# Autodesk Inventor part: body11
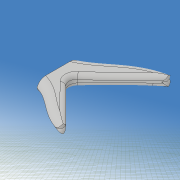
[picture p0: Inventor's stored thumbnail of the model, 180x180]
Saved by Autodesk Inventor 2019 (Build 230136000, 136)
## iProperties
Created: 2020-12
Part Number: body11
Material: 一般
Document SubType Name: Modeling
Designer: kikut
Density: 1 g/cm^3
Appearance: 既定
Mass: 87.6477 g
Surface Area: 156.124 cm^2
Volume: 87.6477 cm^3
Author: kikut
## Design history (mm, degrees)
sketch "スケッチ1"
  geometry: L1 (-100, -20)-(100, -20); L2 (100, -20)-(100, 20); L3 (100, 20)-(-100, 20); L4 (-100, 20)-(-100, -20); L5 (-100, -20)-(100, 20); L6 (100, -20)-(-100, 20); 1 further point
  constraints: 12 end point, 2 midpoint, 2 parallel, 1 horizontal, 1 perpendicular
  dimensions: "d0" = 40 distance of L3.end L1.start; "d1" = 200 distance of L2.end L3.end
extrude "押し出し1" new body sketch "スケッチ1" stored distance "d2" = 60; taper "d3" = 0 deg
sketch "スケッチ2"
  geometry: L1 (0, -60)-(0, 0) reference; L2 (200, -60)-(200, 0) reference; L3 (0, 0)-(200, 0) reference; L4 (200, -60)-(0, -60) reference; L5 (0, -26)-(0, -32); L6 (194, -10)-(194, -13); L7 (194, -13)-(174, -33); L8 (174, -33)-(200, -58); L9 (-20, 20)-(220, 20); L10 (220, 20)-(220, -100); L11 (220, -100)-(-20, -100); L12 (-20, -100)-(-20, 20); 12 further points
  constraints: 16 end point, 4 point on line, 2 parallel, 2 vertical, 1 horizontal, 1 perpendicular, 14 other
  dimensions: "d4" = 32 distance from line of point (32, -12) L1; "d5" = 50 horizontal distance of point (32, -12) point (82, -11); "d6" = 50 horizontal distance of point (132, -17) point (82, -11); "d7" = 12 distance from line of point (32, -12) L3; "d8" = 11 distance from line of point (82, -11) L3; "d10" = 17 distance from line of point (132, -17) L3; "d11" = 26 distance from line of L5.start L3; "d12" = 0 distance from line of point (200, -60) L4; "d13" = 28 distance from line of L5.end L4; "d14" = 12 distance from line of point (28, -48) L4; "d15" = 10 distance from line of point (80, -50) L4; "d16" = 16 distance from line of point (130, -44) L4; "d17" = 28 distance from line of point (28, -48) L1; "d19" = 50 horizontal distance of point (130, -44) point (80, -50); "d20" = 80 distance from line of point (80, -50) L1; "d21" = 6 distance from line of L6.start L2; "d22" = 36 distance from line of point (164, -24) L2; "d23" = 24 distance from line of point (176, -20) L2; "d24" = 10 distance from line of L6.start L3; "d25" = 20 distance from line of point (176, -20) L3; "d26" = 24 distance from line of point (164, -24) L3; "d27" = 40 distance from line of point (160, -40) L2; "d28" = 25 distance from line of point (175, -47.5) L2; "d29" = 12.5 distance from line of point (175, -47.5) L4; "d30" = 20 distance from line of L4 point (160, -40); "d31" = 3 distance of L6.start L6.end; "d32" = 33 distance from line of L7.end L3; "d33" = 26 distance from line of L7.end L2; "d34" = 2 distance of L8.end L2.start; "d35" = 120 distance of L11.end L9.start; "d36" = 240 distance of L10.end L11.end; "d37" = 20 distance between parallel lines of L1 L12; "d38" = 20 distance between parallel lines of L3 L9
extrude "押し出し2" cut sketch "スケッチ2" extent not by distance; stored distance "d39" = 0.02; taper "d40" = 0 deg
sketch "スケッチ8"
  geometry: L1 (-100, -20)-(-100, 20) reference; L2 (100, 20)-(100, -20) reference; L3 (-142.805, 0)-(142.831, 0) reference; L4 (110, 30)-(-110, 30); L5 (-110, 30)-(-110, -30); L6 (-110, -30)-(110, -30); L7 (110, -30)-(110, 30); L8 (110, 30)-(-110, -30); L9 (-110, 30)-(110, -30); L10 (-100, -2)-(-100, 2); L11 (100, -3)-(100, 3); 7 further points
  constraints: 16 end point, 4 point on line, 2 midpoint, 2 parallel, 2 perpendicular, 1 collinear, 1 horizontal, 10 other
  dimensions: "d93" = 2 vertical distance of point (0, 0) L10.end; "d94" = 2 vertical distance of L10.start point (0, 0); "d95" = 35 distance from line of point (-65, -10) L1; "d96" = 0 horizontal distance of point (-65, 10) point (-65, -10); "d97" = 10 vertical distance of point (0, 0) point (-65, -10); "d98" = 10 vertical distance of point (-65, 10) point (0, 0); "d99" = 100 distance from line of point (0, -10) L1; "d100" = 0 horizontal distance of point (0, 10) point (0, -10); "d101" = 10 distance of point (0, -10) point (0, 0); "d102" = 10 distance of point (0, 0) point (0, 10); "d103" = 160 distance from line of point (60, -4) L1; "d104" = 0 horizontal distance of point (60, 4) point (60, -4); "d105" = 4 distance from line of L3 point (60, -4); "d106" = 4 distance from line of L3 point (60, 4); "d107" = 3 distance from line of L11.start L3; "d108" = 3 distance from line of L11.end L3; "d109" = 220 distance of L5.end L6.end; "d110" = 60 distance of L4.end L5.end
extrude "押し出し6" cut sketch "スケッチ8" extent not by distance; stored distance "d111" = 10; taper "d112" = 0 deg
sketch "スケッチ9" dims "d113" = 20, "d114" = 12
  geometry: L1 (-29, -18)-(21, -18); L2 (21, -18)-(21, 22); L3 (21, 22)-(-29, 22); L4 (-29, 22)-(-29, -18); L5 (-29, -18)-(21, 22); L6 (21, -18)-(-29, 22); 2 further points; 1 other entity
  constraints: 12 end point, 2 midpoint, 2 parallel, 1 coincident, 1 horizontal, 1 perpendicular, 2 other
  dimensions: "d115" = 50 distance of L2.end L3.end; "d116" = 40 distance of L1.end L2.end
extrude "押し出し7" cut sketch "スケッチ9" distance "d117" = 150; taper "d118" = 0 deg
fillet "フィレット4" dims "d119" = 4
fillet "フィレット5" dims "d120" = 4
fillet "フィレット6" dims "d121" = 2
node "作業平面2"
sketch "スケッチ10"
  geometry: L1 (0, -41.439)-(0, 38.458) reference; L2 (141.833, 0)-(-140.631, 0) reference; L3 (82.55, 12.983)-(81.45, -4.983); A1 r 9 centre (82, 4) between (82.55, 12.983) and (81.45, -4.983); 1 further point
  constraints: 2 end point, 2 point on circle, 1 centre point
  dimensions: "d123" = 82 distance from line of L1 A1.centre; "d124" = 4 distance from line of L2 A1.centre; "d125" = 9 radius of A1; "d126" = 180 deg dimension on A1.centre L3.end L3.start; "d127" = 90 deg dimension on L3.end point (0, 0) A1.centre
revolve "回転1" sketch "スケッチ10" stored, may be unused: angle "d128" = 90 deg
mirror "ミラー1"
sketch "スケッチ11"
  geometry: L1 (-70, 30)-(-110, 30); L2 (-110, 30)-(-110, -30); L3 (-110, -30)-(-70, -30); L4 (-70, -30)-(-70, 30); L5 (0, -40.648)-(0, 34.486) reference; L6 (140.69, 0)-(-139.196, 0) reference; L7 (120, 53.792)-(-120, 53.792); L8 (-120, 53.792)-(-120, -46.208); L9 (-120, -46.208)-(120, -46.208); L10 (120, -46.208)-(120, 53.792); 1 further point
  constraints: 16 end point, 4 parallel, 2 horizontal, 2 perpendicular, 2 other
  dimensions: "d130" = 40 distance of L1.start L1.end; "d131" = 60 distance of L3.end L1.start; "d132" = 100 distance of L9.end L7.start; "d133" = 240 distance of L7.start L7.end; "d138" = 70 distance between parallel lines of L4 L5
extrude "押し出し8" cut sketch "スケッチ11" stored distance "d134" = 40; taper "d135" = 0 deg
node "ソリッド1"
other parameters: "d122" = -1
